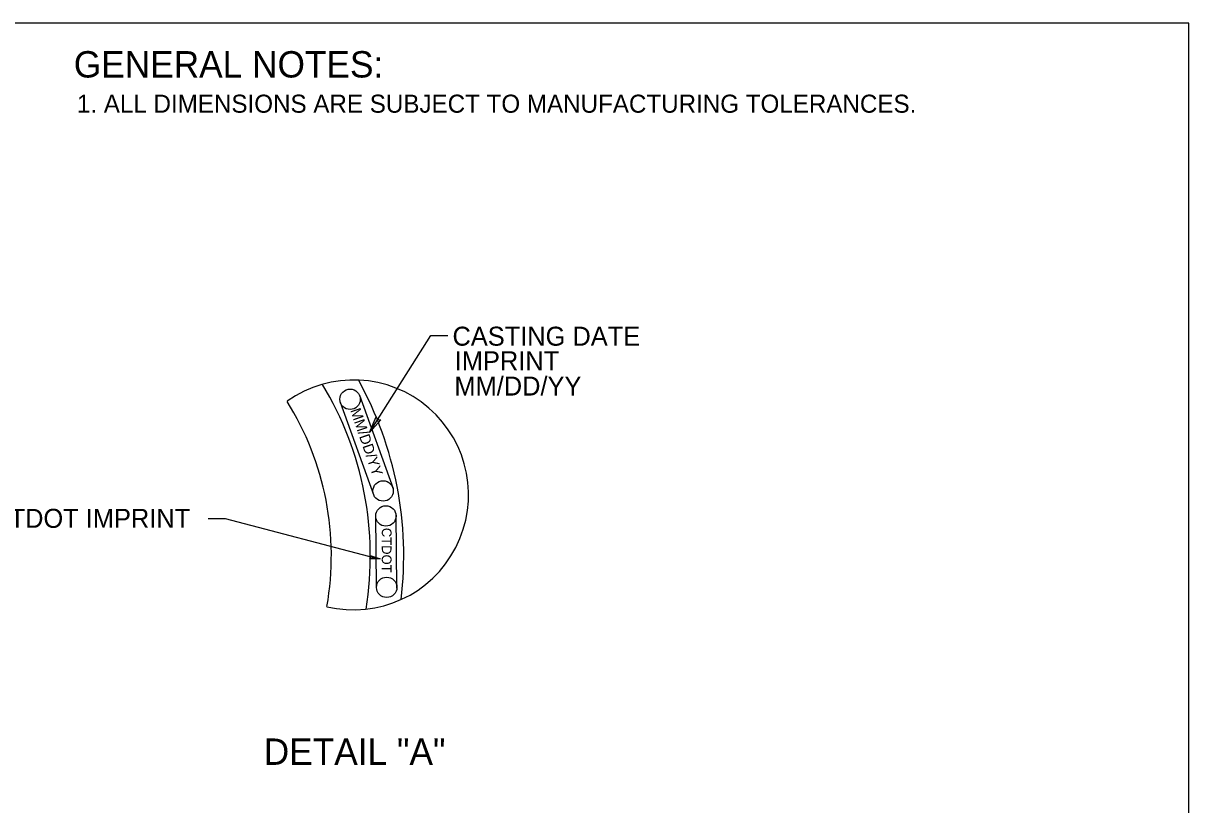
# Model space of a CAD drawing. Extents: x 0 to 31.8, y -0.5 to 20.8.
# Drawn here: x 24.01 to 31.75, y 15.56 to 20.75 of the extents above; entities that cross this region are included whole.
import ezdxf

# ---------------------------------------------------------------- set-up
doc = ezdxf.new("R2010")
doc.units = 0
for name, color, linetype in [('CT_Border_Perimeter_Shape', 7, 'Continuous'), ('CT_CSHT_GeneralLabel', 7, 'Continuous'), ('CT_Dimensions', 7, 'Continuous'), ('sb_Detail Text', 7, 'Continuous'), ('sb_Existing Structural Steel', 7, 'Continuous')]:
    doc.layers.add(name, color=color, linetype=linetype)

msp = doc.modelspace()

# ---------------------------------------------------------------- linework, layer by layer
at = {"layer": 'CT_Border_Perimeter_Shape'}
msp.add_lwpolyline([(0, 0), (31.7501, 0), (31.7501, 20.75), (0, 20.75)], close=True, dxfattribs=at)
at = {"layer": 'CT_Dimensions'}
for p, q in [((26.3112, 18.0331), (26.7189, 18.6775)), ((26.7189, 18.6775), (26.8319, 18.6775)), ((26.3112, 18.0331), (26.3554, 18.138)), ((26.3871, 18.118), (26.3112, 18.0331)), ((25.2415, 17.4633), (25.3546, 17.4633)), ((25.3546, 17.4633), (26.347, 17.2015)), ((26.3825, 17.1945), (26.3114, 17.1941)), ((26.3151, 17.2172), (26.3825, 17.1945))]:
    msp.add_line(p, q, dxfattribs=at)
for centre, radius, start, end in [((26.3806, 18.1427), 0.0256, 190.64706, 284.71174), ((26.3025, 17.2074), 0.016, 303.77672, 37.8414)]:
    msp.add_arc(centre, radius, start, end, dxfattribs=at)
at = {"layer": 'sb_Existing Structural Steel'}
for p, q in [((26.2451, 18.2819), (26.468, 17.6612)), ((26.1177, 18.2342), (26.3415, 17.6145)), ((26.3579, 17.0061), (26.3528, 17.4868)), ((26.4924, 16.9993), (26.488, 17.4911))]:
    msp.add_line(p, q, dxfattribs=at)
for centre in [(26.1827, 18.2538), (26.402, 17.6452), (26.4206, 17.4793), (26.4259, 17.0055)]:
    msp.add_circle(centre, 0.0677, dxfattribs=at)
for centre, radius, start, end in [((26.2063, 17.6191), 0.763, 256.57277, 125.32527), ((24.1201, 17.2144), 2.1972, 350.74196, 31.21758), ((24.1201, 17.2144), 2.4189, 353.11961, 28.79059), ((24.1201, 17.2144), 1.9384, 349.99635, 31.9567)]:
    msp.add_arc(centre, radius, start, end, dxfattribs=at)

# ---------------------------------------------------------------- texts
at = {"layer": 'CT_CSHT_GeneralLabel'}
for s, height, p in [('GENERAL NOTES:', 0.175, (24.3486, 20.3902)), ('1. ALL DIMENSIONS ARE SUBJECT TO MANUFACTURING TOLERANCES.', 0.12, (24.3694, 20.1564)), ('DETAIL "A"', 0.175, (25.6097, 15.8271))]:
    msp.add_text(s, height=height, dxfattribs=at).set_placement(p)
at = {"layer": 'CT_Dimensions'}
for s, height, p in [('CASTING DATE', 0.126098, (26.8627, 18.6098)), ('IMPRINT', 0.1261, (26.8779, 18.4466)), ('MM/DD/YY', 0.1261, (26.8754, 18.2789)), ('CTDOT IMPRINT', 0.126098, (23.8007, 17.4006))]:
    msp.add_text(s, height=height, dxfattribs=at).set_placement(p)
at = {"layer": 'sb_Detail Text'}
for s, height, rotation, p in [('MM/DD/YY', 0.07015, 288.9464, (26.1829, 18.181)), ('CTDOT ', 0.06457, 270, (26.3935, 17.4007))]:
    msp.add_text(s, height=height, rotation=rotation, dxfattribs=at).set_placement(p)

doc.saveas('drawing.dxf')
